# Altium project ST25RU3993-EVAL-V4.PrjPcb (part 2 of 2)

## Sheet Supply-V4.SchDoc
size A4; SheetNumber: 6; PageSetup: Record=PageOptions¦CenterHorizontal=True¦CenterVertical=True¦PrintScale=0.97¦XCorrection=1.00¦YCorrection=1.00¦PrintKind=0¦BorderSize=5000000¦LeftOffset=0¦BottomOffset=0¦Orientation=2¦PaperLength=1000¦PaperWidth=1000¦Scale=100¦PaperSource=7¦PrintQuality=-4¦MediaType=1¦DitherType=10¦PaperKind=A4¦PrintScaleMode=1
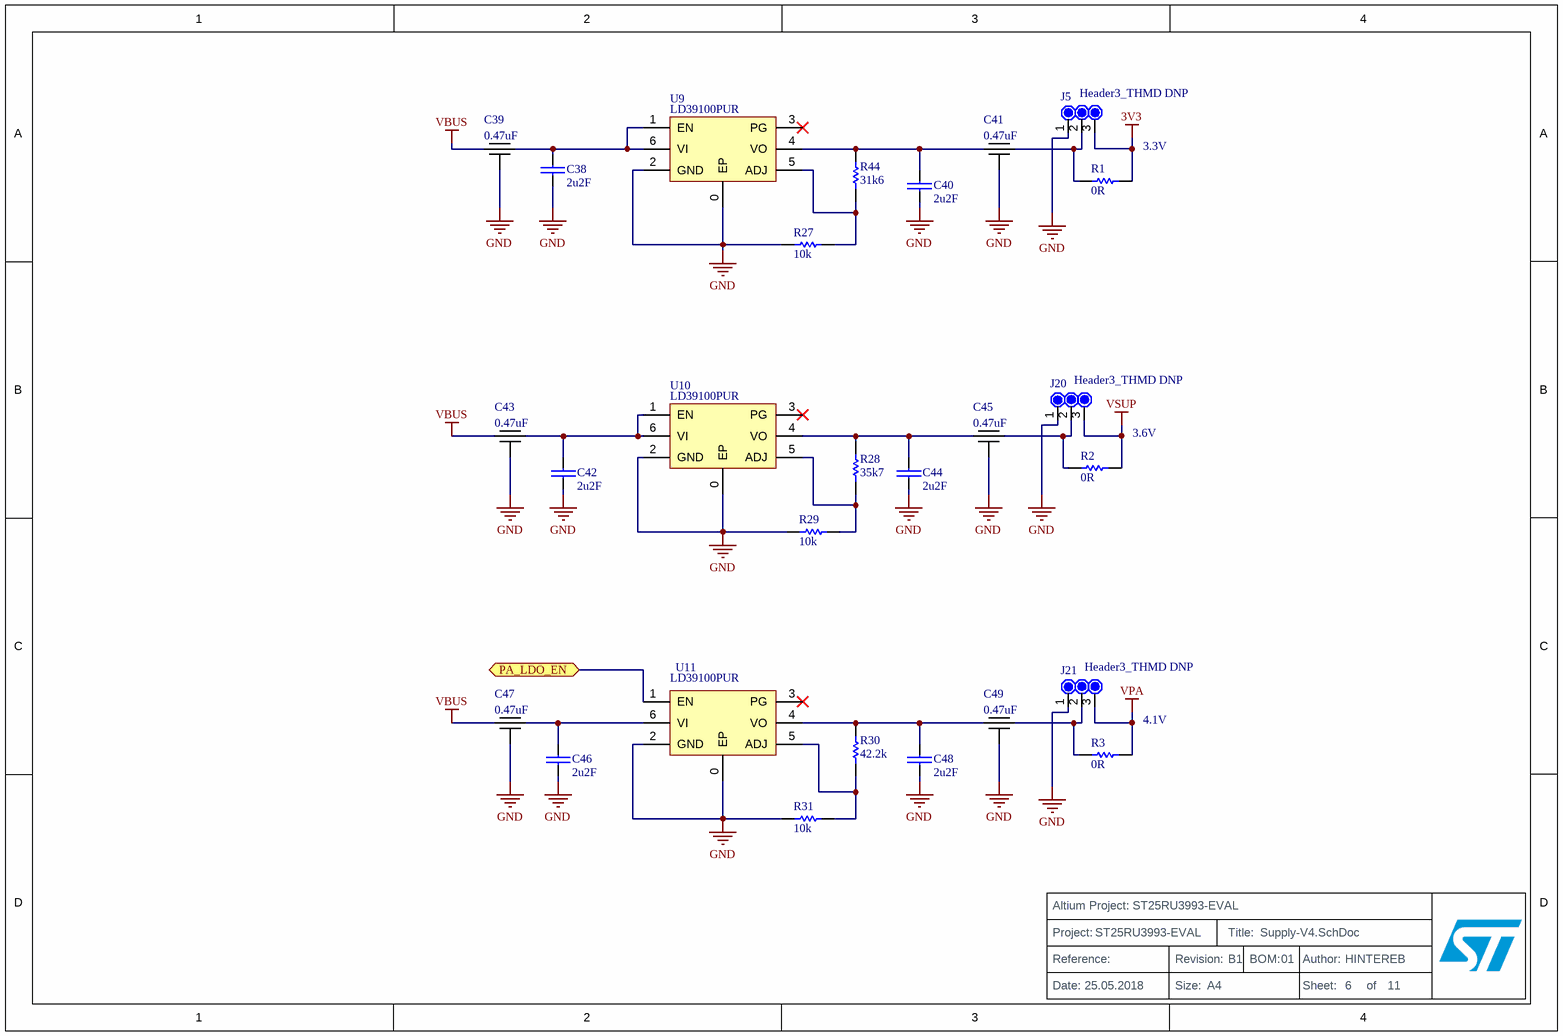
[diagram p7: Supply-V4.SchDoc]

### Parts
C38  2u2F  [C0402-RF]
C39  0.47uF  [NFM18PS]
C40  2u2F  [C0402-RF]
C41  0.47uF  [NFM18PS]
C42  2u2F  [C0402-RF]
C43  0.47uF  [NFM18PS]
C44  2u2F  [C0402-RF]
C45  0.47uF  [NFM18PS]
C46  2u2F  [C0402-RF]
C47  0.47uF  [NFM18PS]
C48  2u2F  [C0402-RF]
C49  0.47uF  [NFM18PS]
J5  Header3_THMD DNP  [PLUG_THMD_STRIP3]  (no BOM)
J20  Header3_THMD DNP  [PLUG_THMD_STRIP3]  (no BOM)
J21  Header3_THMD DNP  [PLUG_THMD_STRIP3]  (no BOM)
R1  0R  [R0603-ss]
R2  0R  [R0603-ss]
R3  0R  [R0603-ss]
R27  10k  [R0402-RF]
R28  35k7  [R0402-RF]
R29  10k  [R0402-RF]
R30  42.2k  [R0402-RF]
R31  10k  [R0402-RF]
R44  31k6  [R0402-RF]
TitleBlock4  Title_Block  (value not drawn)  (no BOM)
U9  LD39100PUR  [LD39100PUR]
U10  LD39100PUR  [LD39100PUR]
U11  LD39100PUR  [LD39100PUR]

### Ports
PA_LDO_EN (bidir)

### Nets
3V3: J5.3 R1.1
GND: C38.2 C39.2 C40.2 C41.2 C42.2 C43.2 C44.2 C45.2 C46.2 C47.2 C48.2 C49.2 J5.1 J20.1 J21.1 R27.1 R29.1 R31.1 U9.0(EP) U9.2(GND) U10.0(EP) U10.2(GND) U11.0(EP) U11.2(GND)
VBUS: C39.1 C43.1 C47.1
VPA: J21.3 R3.1
VSUP: J20.3 R2.1
PA_LDO_EN: U11.1(EN) ; port PA_LDO_EN
NetC38_1: C38.1 C39.3 U9.1(EN) U9.6(VI)
NetC40_1: C40.1 C41.1 R44.2 U9.4(VO)
NetC41_3: C41.3 J5.2 R1.2
NetC42_1: C42.1 C43.3 U10.1(EN) U10.6(VI)
NetC44_1: C44.1 C45.1 R28.2 U10.4(VO)
NetC45_3: C45.3 J20.2 R2.2
NetC46_1: C46.1 C47.3 U11.6(VI)
NetC48_1: C48.1 C49.1 R30.2 U11.4(VO)
NetC49_3: C49.3 J21.2 R3.2
NetR27_2: R27.2 R44.1 U9.5(ADJ)
NetR28_1: R28.1 R29.2 U10.5(ADJ)
NetR30_1: R30.1 R31.2 U11.5(ADJ)

Not connected (* = marked no-connect by the designer): U9 3(PG)*; U10 3(PG)*; U11 3(PG)*

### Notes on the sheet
- 3.3V
- 3.6V
- 4.1V

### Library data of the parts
C38 C40 C42 C44 C46 C48 = GRM155R60J225ME95D: CAP CER 2.2UF 6.3V  X5R  0402; Manufacturer: Murata Electronics North America; Tolerance: ±20%; Notification: Current market demand for these product types have resulted in fluctuating and extending lead times. Lead times may differ.; Exact Component Match: no
C39 C41 C43 C45 C47 C49 = NFM18PS474R0J3D: CAP FEEDTHRU 0.47UF 6.3V 0603; Manufacturer: Murata Electronics North America; Capacitance: 0.47µF; Tolerance: ±20%; Current: 2A; DC Resistance (DCR) (Max): 30 mOhm; Type: Polymer; ESR (Equivalent Series Resistance): 70 mOhm; Lifetime @ Temp.: 1000 Hrs @ 105°C; Ripple Current - High Frequency: 1A @ 100kHz; Surface Mount Land Size: 0.287" L x 0.169" W (7.30mm x 4.30mm); Exact Component Match: no
J5 J20 J21 = Pin_Header_x3: Manufacturer: Wurth Electronics Inc.; Manufacturer Part Number: 61300311121; Connector Type: Header; Pitch - Mating: 0.100" (2.54mm); Number of Positions: 3; Number of Positions Loaded: All; Style: Board to Board or Cable; Shrouding: Unshrouded; Contact Length - Mating: 0.236" (6.00mm); Contact Length - Post: 0.118" (3.00mm); Overall Contact Length: 0.454" (11.54mm); Material Flammability Rating: UL94 V-0; Current Rating: 3A; Voltage Rating: 250V; Exact Component Match: no
R1-R3 = RC0603JR-070RL: RES SMD 0.0OHM JUMPER 1/10W 0603; Manufacturer: Yageo; Exact Component Match: no
R27 R29 R31 = RC0402FR-0710KL: RES SMD 10K OHM 1% 1/16W 0402; Manufacturer 1: Yageo; Power (Watts): 0.063W, 1/16W; Temperature Coefficient: ±100ppm/°C; Exact Component Match: no
R28 = RC0402FR-0735K7L: RES SMD 35.7K OHM 1% 1/16W 0402; Manufacturer: Yageo; Power (Watts): 0.063W, 1/16W; Temperature Coefficient: ±100ppm/°C; Exact Component Match: no
R30 = ERJ-2RKF4222X: RES SMD 42.2K OHM 1% 1/10W 0402; Manufacturer: Panasonic Electronic Components; Power (Watts): 0.1W, 1/10W; Temperature Coefficient: ±100ppm/°C; Exact Component Match: no
R44 = RC0402FR-0731K6L: RES SMD 31.6K OHM 1% 1/16W 0402; Manufacturer: Yageo; Power (Watts): 0.063W, 1/16W; Temperature Coefficient: ±100ppm/°C; Exact Component Match: no
TitleBlock4 = Title_Block: Exact Component Match: no
U9-U11 = LD39100PUR: IC REG LDO ADJ 1A 6DFN; Manufacturer: STMicroelectronics; Regulator Topology: Positive Adjustable; Voltage - Output: 0.8 V ~ 4.5 V; Voltage - Dropout (Typical): 0.2V @ 1A; Number of Regulators: 1; Voltage - Input: 1.5 V ~ 5.5 V; Exact Component Match: no

## Sheet Title_Page-V4.SchDoc
size A4
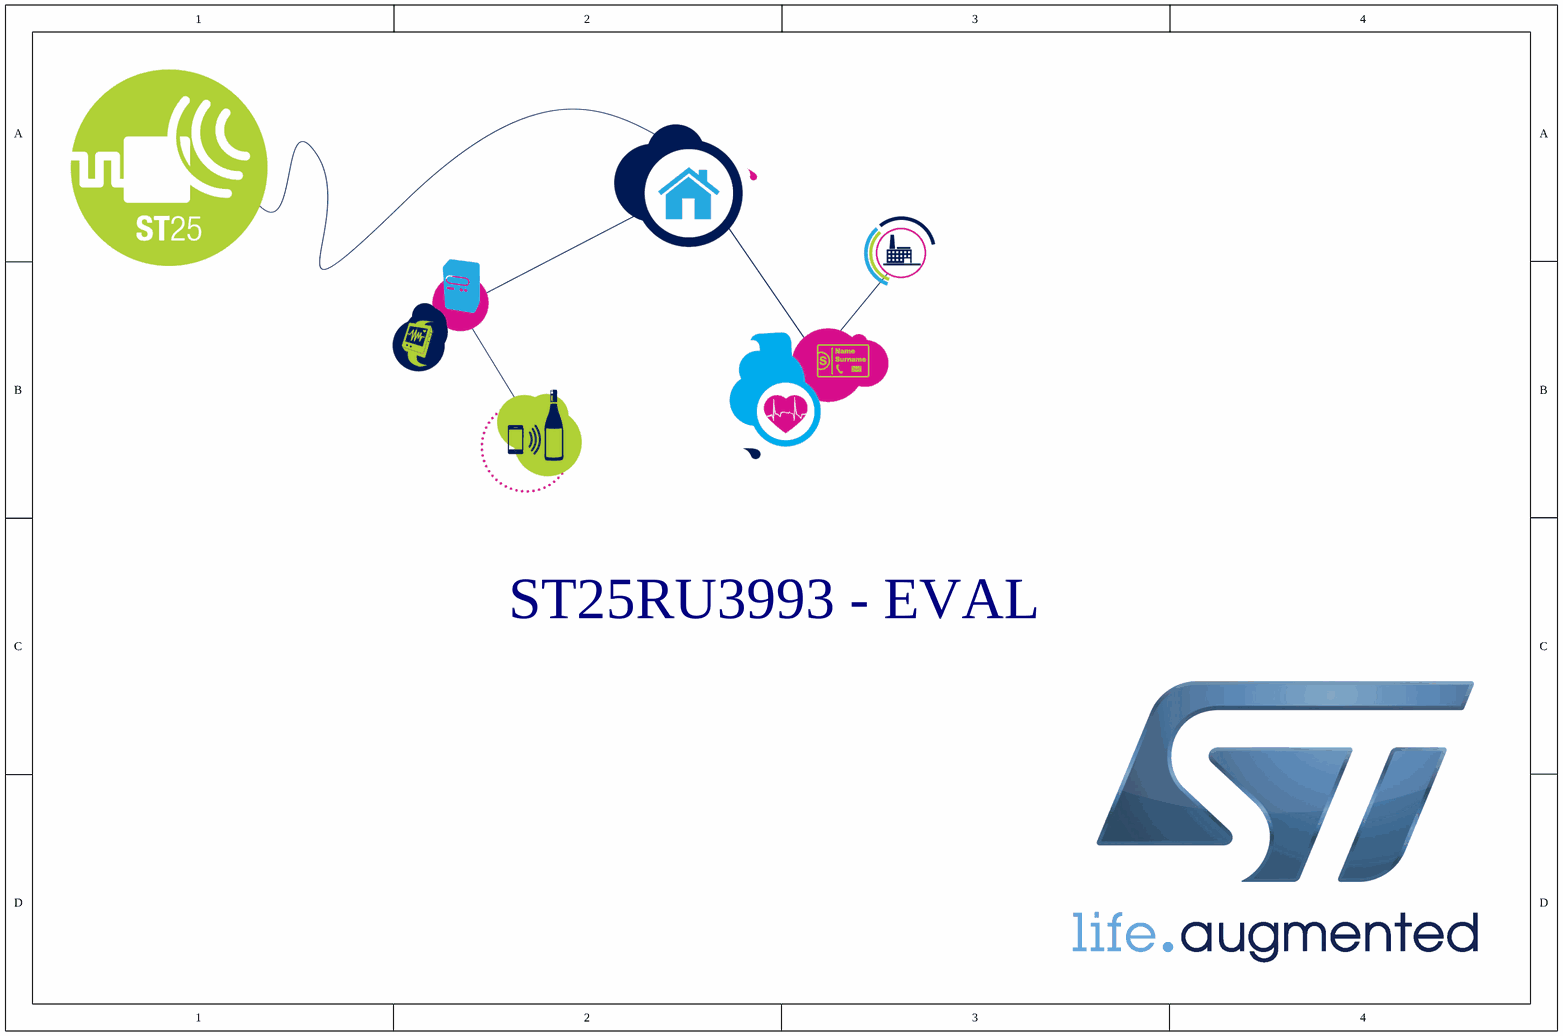
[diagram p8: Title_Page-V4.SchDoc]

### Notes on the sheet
- ST25RU3993 - EVAL

## Sheet USB_Interface-V4.SchDoc
size A4; SheetNumber: 8
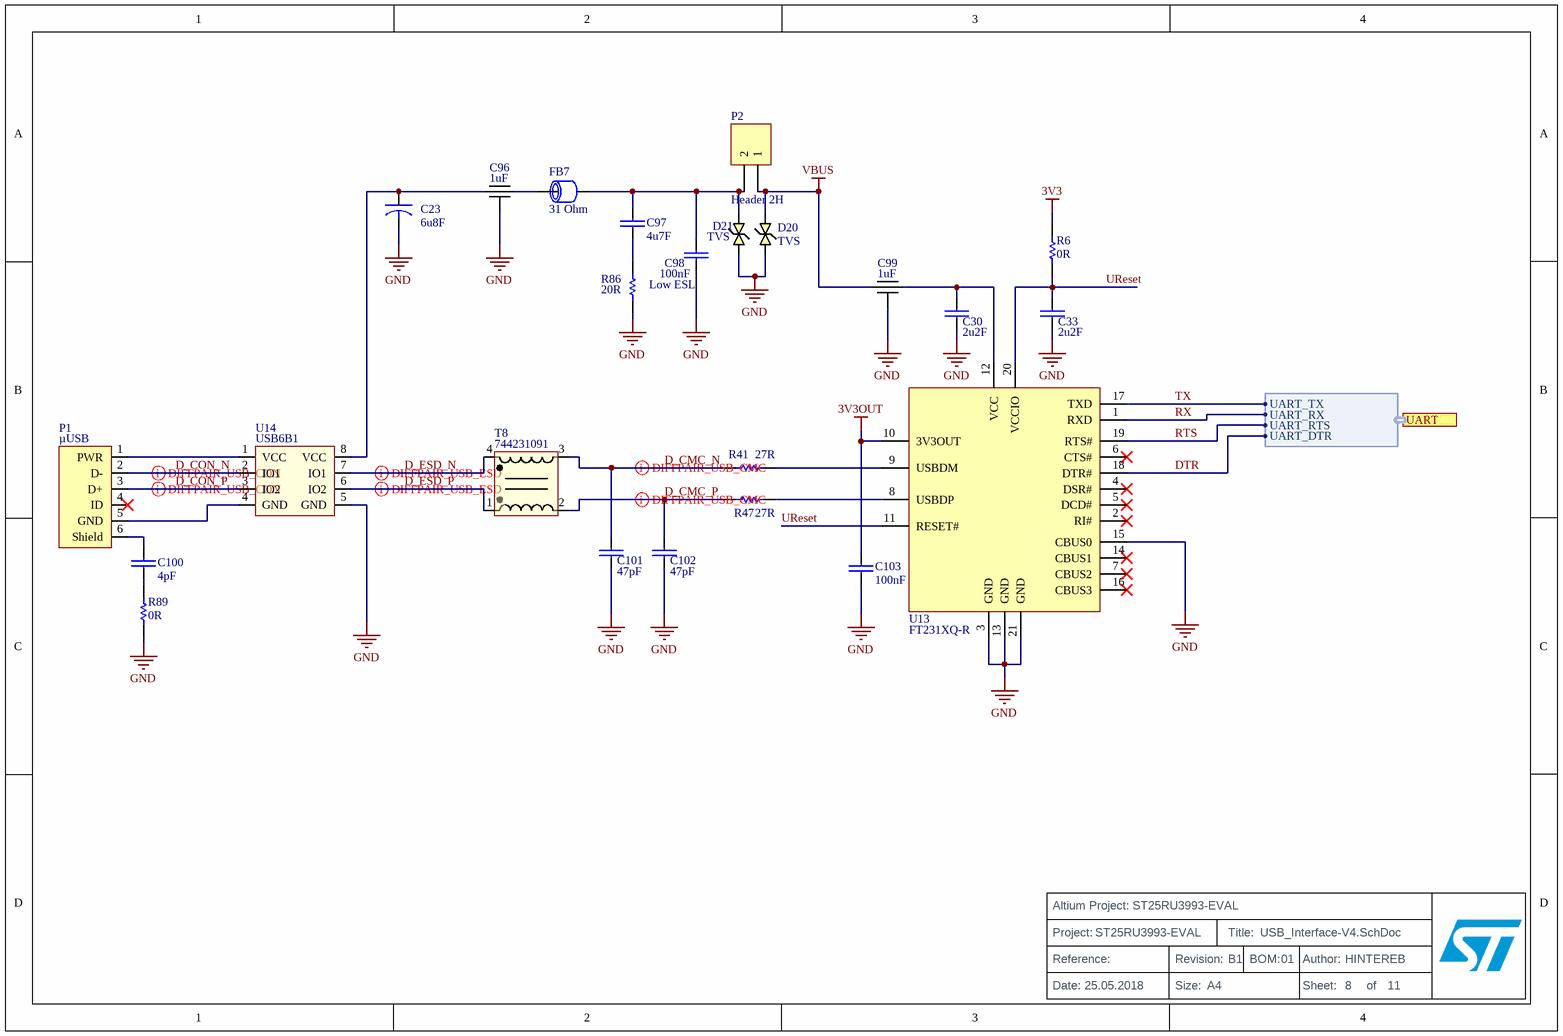
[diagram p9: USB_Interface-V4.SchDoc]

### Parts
C23  6u8F  [2917(7343)]
C30  2u2F  [C0201-RF]
C33  2u2F  [C0201-RF]
C96  1uF  [NFM21PC]
C97  4u7F  [C0603-ss]
C98  100nF  Features: Low ESL  [C0402-LLL]
C99  1uF  [NFM21PC]
C100  4pF  [C0402-ss]
C101  47pF  [C0402-RF]
C102  47pF  [C0402-RF]
C103  100nF  [C0201-ss]
D20  TVS  [DFN35P60X33-2N]
D21  TVS  [DFN35P60X33-2N]
FB7  31 Ohm  [NFZ32BW310HN11]
P1  µUSB  [µUSB Molex]
P2  Header 2H  [PLUG_THMD_STRIP2 - 90°]
R6  0R  [R0402-RF]
R41  27R  [R0402-RF]
R47  27R  [R0402-RF]
R86  20R  [R0402-RF]
R89  0R  [R0402-RF]
T8  744231091  [744231091]
TitleBlock10  Title_Block  (value not drawn)  (no BOM)
U13  FT231XQ-R  [FT231XQ]
U14  USB6B1  [SO-8]

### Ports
UART (harness Harness_UART)

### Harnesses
Harness_UART: UART_RTS, UART_DTR, UART_TX, UART_RX

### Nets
3V3: R6.1
3V3OUT: C103.1 U13.10(3V3OUT)
GND: C23.2 C30.2 C33.2 C96.2 C98.2 C99.2 C101.2 C102.2 C103.2 D20.2 D21.2 R86.1 R89.2 U13.3(GND) U13.13(GND) U13.15(CBUS0) U13.21(GND) U14.5(GND)
VBUS: C99.1 D20.1 P2.1
D_CMC_N: C101.1 R41.1 T8.3
D_CMC_P: C102.1 R47.1 T8.2
D_CON_N: P1.2(D-) U14.2(IO1)
D_CON_P: P1.3(D+) U14.3(IO2)
D_ESD_N: T8.4 U14.7(IO1)
D_ESD_P: T8.1 U14.6(IO2)
DTR: U13.18(DTR#) ; port UART.UART_DTR
RTS: U13.19(RTS#) ; port UART.UART_RTS
RX: U13.1(RXD) ; port UART.UART_RX
TX: U13.17(TXD) ; port UART.UART_TX
UReset: C33.1 R6.2 U13.11(RESET#) U13.20(VCCIO)
NetC23_1: C23.1 C96.1 U14.8(VCC)
NetC30_1: C30.1 C99.3 U13.12(VCC)
NetC96_3: C96.3 FB7.1
NetC97_1: C97.1 C98.1 D21.1 FB7.2 P2.2
NetC97_2: C97.2 R86.2
NetC100_1: C100.1 P1.6(Shield)
NetC100_2: C100.2 R89.1
NetP1_1: P1.1(PWR) U14.1(VCC)
NetP1_5: P1.5(GND) U14.4(GND)
NetR41_2: R41.2 U13.9(USBDM)
NetR47_2: R47.2 U13.8(USBDP)

Not connected (* = marked no-connect by the designer): P1 4(ID)*; U13 2(RI#)* 4(DSR#)* 5(DCD#)* 6(CTS#)* 7(CBUS2)* 14(CBUS1)* 16(CBUS3)*

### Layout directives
differential pair: D_CMC_N, D_CMC_P, D_CON_N, D_CON_P, D_ESD_N, D_ESD_P

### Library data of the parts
C23 = ECASD41C685M070K00: CAP ALUM POLY 6.8UF 20% 16V SMD; Manufacturer: Murata Electronics North America; Type: Polymer; ESR (Equivalent Series Resistance): 70 mOhm; Lifetime @ Temp.: 1000 Hrs @ 105°C; Ripple Current - High Frequency: 1A @ 100kHz; Surface Mount Land Size: 0.287" L x 0.169" W (7.30mm x 4.30mm); Exact Component Match: no
C30 C33 = GRM033R60J225ME15D: CAP CER 2.2UF 6.3V X5R 0201; Manufacturer 1: Murata Electronics North America; Capacitance: 2.2µF; Tolerance: ±20%; Exact Component Match: no
C96 C99 = NFM21PC105B1A3D: CAP FEEDTHRU 1UF 20% 10V 0805; Manufacturer: Murata Electronics North America; Capacitance: 1µF; Current: 4A; DC Resistance (DCR) (Max): 20 mOhm; Coupler Type: Standard; Frequency: 1.7GHz ~ 2.2GHz; Coupling Factor: 19.9dB; Power - Max: 2W; Return Loss: 22.5dB; Exact Component Match: no
C97 = GRM188R61A475KE15D: CAP CER 4.7UF 10V X5R 0603; Manufacturer: Murata Electronics North America; Tolerance: ±10%; Notification: Current market demand for these product types have resulted in fluctuating and extending lead times. Lead times may differ.; Exact Component Match: no
C98 = LLL153C80J104ME01E: CAP CER 0.1UF 6.3V X6S 0204; Manufacturer: Murata Electronics North America; Tolerance: ±20%; Type: Steering (Rail to Rail); Voltage - Reverse Standoff (Typ): 5.25V; Voltage - Breakdown (Min): 6V; Power - Peak Pulse: 500W; Power Line Protection: Yes; Exact Component Match: no
C100 = GRM1555C1H4R0CA01D: CAP CER 4PF 50V C0G/NP0 0402; Manufacturer: Murata Electronics North America; Tolerance: ±0.25pF; Temperature Coefficient: C0G, NP0; Notification: Current market demand for these product types have resulted in fluctuating and extending lead times. Lead times may differ.; Exact Component Match: no
C101 C102 = GRM1555C1H470FA01D: CAP CER 47PF 50V NP0 0402; Manufacturer: Murata Electronics North America; Tolerance: ±1%; Temperature Coefficient: C0G, NP0; Exact Component Match: no
C103 = GRM033C80J104KE15D: CAP CER 0.1UF 6.3V X6S 0201; Manufacturer 1: Murata Electronics North America; Capacitance: 0.10µF; Tolerance: ±10%; Exact Component Match: no
D20 D21 = ESDAXLC6-1BU2: TVS DIODE 3VWM 17VC ST0201; Manufacturer: STMicroelectronics; Type: Zener; Voltage - Reverse Standoff (Typ): 3V; Voltage - Breakdown (Min): 6V; Voltage - Clamping (Max) @ Ipp: 17V; Current - Peak Pulse (10/1000µs): 1A (8/20µs); Power - Peak Pulse: 40W; Power Line Protection: No; Capacitance @ Frequency: 0.4pF @ 200MHz ~ 3GHz; Tolerance: ±1%; Power (Watts): 0.1W, 1/10W; Temperature Coefficient: ±100ppm/°C
FB7 = NFZ32BW310HN11L: FERRITE BEAD 31 OHM 2SMD 1LN; Manufacturer: Murata Electronics North America; Current Rating (Max): 1.2A; DC Resistance (DCR) (Max): 186 mOhm; Exact Component Match: no
P1 = µUSB: Micro USB Connector; Manufacturer: Molex, LLC; Manufacturer Part Number: 1050170001; Connector Type: USB - micro B; Number of Contacts: 5; Gender: Receptacle; Specifications: USB 2.0; Number of Ports: 1; Current Rating: 1A, 1.8A; Voltage - Rated: 30VAC; Mating Cycles: 10000; Shielding: Shielded; Material Flammability Rating: UL94 V-0; Exact Component Match: no
P2 = Header 2H: Header, 2-Pin, Right Angle; Exact Component Match: no
R6 R89 = RC0402JR-070RL: RES SMD 0.0OHM JUMPER 1/16W 0402; Manufacturer: Yageo; Resistance (Ohms): 0.0; Power (Watts): 0.063W, 1/16W; Exact Component Match: no
R41 R47 = RC0402FR-0727RL: RES SMD 27 OHM 1% 1/16W 0402; Manufacturer: Yageo; Resistance (Ohms): 27; Power (Watts): 0.063W, 1/16W; Temperature Coefficient: ±100ppm/°C; Exact Component Match: no
R86 = RC0402JR-0720RL: RES SMD 20 OHM 5% 1/16W 0402; Manufacturer 1: Yageo; Resistance (Ohms): 20; Power (Watts): 0.063W, 1/16W; Temperature Coefficient: ±100ppm/°C; Frequency: 915MHz Center; Bandwidth: 26MHz; Filter Type: Low Pass; Insertion Loss: 0.5dB; Exact Component Match: no
T8 = 744231091: CHOKE COM MODE 90 OHM .37A SMD; Manufacturer: Wurth Electronics Inc.; Filter Type: Signal Line; Number of Lines: 2; Current Rating (Max): 370mA; DC Resistance (DCR) (Max): 300 mOhm; Voltage Rating - DC: 50V; Exact Component Match: no
TitleBlock10 = Title_Block: Exact Component Match: no
U13 = FT231XQ-R: IC USB SERIAL FULL UART 20QFN; Manufacturer: FTDI, Future Technology Devices International Ltd; Function: Bridge, USB to UART; Standards: USB 2.0; Voltage - Supply: 3.3 V ~ 5 V; Current - Supply: 8mA; Exact Component Match: no
U14 = USB6B1RL: TVS DIODE 5.25VWM 8SOIC; Manufacturer: STMicroelectronics; Voltage - Reverse Standoff (Typ): 5.25V; Voltage - Breakdown (Min): 6V; Power - Peak Pulse: 500W; Power Line Protection: Yes; Exact Component Match: no

## Sheet Bluetooth-V4.SchDoc
size A4; SheetNumber: 10
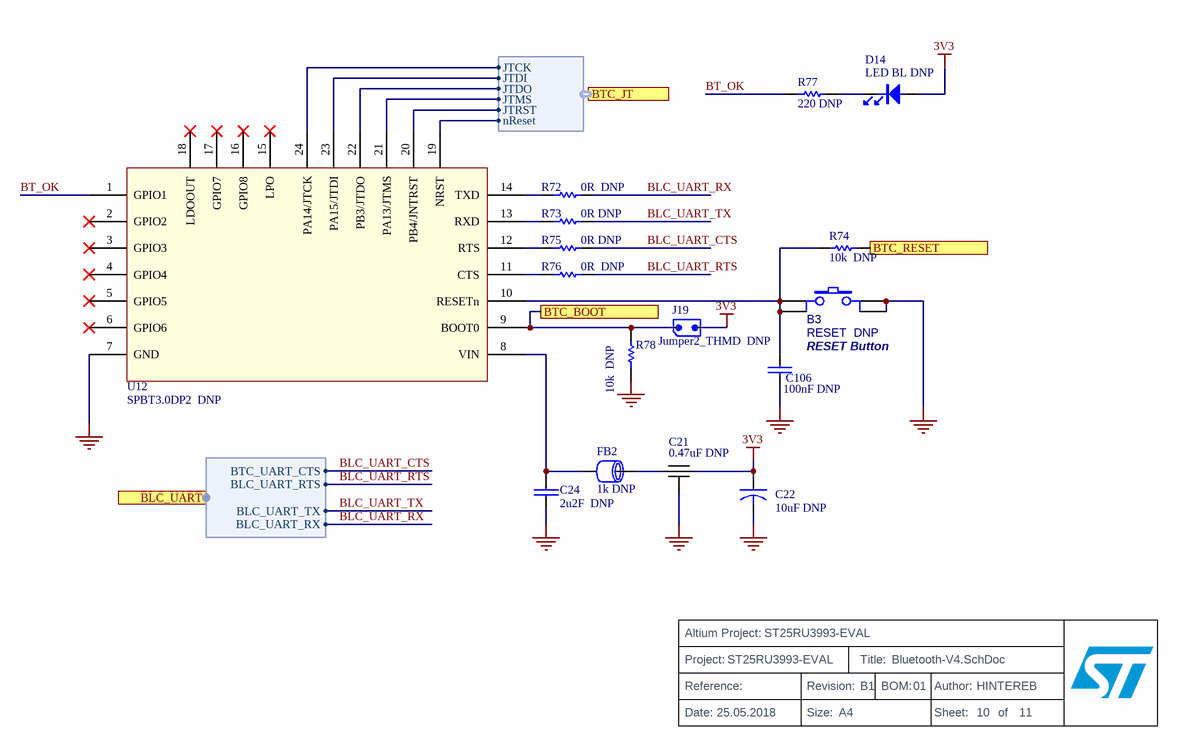
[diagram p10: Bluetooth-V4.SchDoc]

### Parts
B3  RESET  DNP  [SW_SPST_KMR211G]
C21  0.47uF DNP  [NFM18PS]
C22  10uF DNP  [2917(7343)]
C24  2u2F  DNP  [C0201-RF]
C106  100nF DNP  [C0402-RF]
D14  LED BL DNP  [LNJ947W8CRA]
FB2  1k DNP  [L0402-RF]
J19  Jumper2_THMD  DNP  [PLUG_THMD_STRIP2 - DNP]
R72  0R  DNP  [R0402-RF]
R73  0R DNP  [R0402-RF]
R74  10k  DNP  [R0402-RF]
R75  0R DNP  [R0402-RF]
R76  0R  DNP  [R0402-RF]
R77  220 DNP
R78  10k  DNP  [R0402-RF]
TitleBlock9  Title_Block  (value not drawn)  (no BOM)
U12  SPBT3.0DP2  DNP  [SPBT3.0DP2]

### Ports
BLC_UART (harness Harness_UART_BT), BTC_BOOT, BTC_JT (harness Harness_BTC_JT), BTC_RESET

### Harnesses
Harness_UART_BT: BLC_UART_RTS, BTC_UART_CTS, BLC_UART_TX, BLC_UART_RX
Harness_BTC_JT: JTMS, JTRST, nReset, JTDO, JTDI, JTCK

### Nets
3V3: C21.1 C22.1 D14.1 J19.2
GND: B3.2 B3.3 C21.2 C22.2 C24.2 C106.2 R78.1 U12.7(GND)
BLC_UART_CTS: R75.2 ; port BLC_UART.BTC_UART_CTS
BLC_UART_RTS: R76.2 ; port BLC_UART.BLC_UART_RTS
BLC_UART_RX: R72.2 ; port BLC_UART.BLC_UART_RX
BLC_UART_TX: R73.2 ; port BLC_UART.BLC_UART_TX
BT_OK: R77.1 U12.1(GPIO1)
JTCK: U12.24(PA14/JTCK) ; port BTC_JT.JTCK
JTDI: U12.23(PA15/JTDI) ; port BTC_JT.JTDI
JTDO: U12.22(PB3/JTDO) ; port BTC_JT.JTDO
JTMS: U12.21(PA13/JTMS) ; port BTC_JT.JTMS
JTRST: U12.20(PB4/JNTRST) ; port BTC_JT.JTRST
nReset: U12.19(NRST) ; port BTC_JT.nReset
NetB3_1: B3.1 B3.4 C106.1 R74.2 U12.10(RESETn)
NetC21_3: C21.3 FB2.1
NetC24_1: C24.1 FB2.2 U12.8(VIN)
NetD14_2: D14.2 R77.2
NetJ19_1: J19.1 R78.2 U12.9(BOOT0) ; port BTC_BOOT
NetR72_1: R72.1 U12.14(TXD)
NetR73_1: R73.1 U12.13(RXD)
NetR74_1: R74.1 ; port BTC_RESET
NetR75_1: R75.1 U12.12(RTS)
NetR76_1: R76.1 U12.11(CTS)

Not connected (* = marked no-connect by the designer): U12 2(GPIO2)* 3(GPIO3)* 4(GPIO4)* 5(GPIO5)* 6(GPIO6)* 15(LPO)* 16(GPIO8)* 17(GPIO7)* 18(LDOOUT)*

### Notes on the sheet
- RESET Button

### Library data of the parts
B3 = SW-PUSH-CMS_BLACK_1: Non-Open Push-Button 0.1A 24V; Manufacturer 1: C&K Components; Manufacturer Part Number 1: KMR211NG LFS; Circuit: SPST-NO; Switch Function: Off-Mom; Contact Rating @ Voltage: 0.05A @ 32VDC; Actuator Type: Standard; Actuator Height off PCB, from Pins: 1.90mm; Actuator Orientation: Top Actuated; Outline: 4.60mm x 2.80mm; Illumination: Non-Illuminated; Operating Force: 120gf; Switch Travel: 0.20mm; Mechanical Life: 200,000 Cycles; Exact Component Match: no
C21 = NFM18PS474R0J3D: as C39 on sheet Supply-V4
C22 = ECASD41C106M060K00: CAP POLYMER 10UF 20% 16V SMD; Manufacturer: Murata; Product Training Modules: Polymer Aluminum Electrolytic Capacitors Using Murata's Polymer Aluminum Capacitors to Replace Tantalum; Catalog Drawings: ECAS Series End_D4 ECAS Series Side; Featured Product: ECAS Series Polymer Aluminum Electrolytic Capacitors; EDA / CAD Models: Download from Accelerated Designs; Capacitance: 10µF; ESR (Equivalent Series Resistance): 60 mOhm @ 100kHz; Lifetime @ Temp.: 1000 Hrs @ 105°C; Polarization: Polar; Ripple Current: 1A; Surface Mount Land Size: 0.287" L x 0.169" W (7.30mm x 4.30mm); Online Catalog: ECAS Series; Other Names: 490-5482-2; Exact Component Match: no
C24 = GRM033R60J225ME15D: as C30 on sheet USB_Interface-V4
C106 = GRM155R71C104KA88D: CAP CER 0.1UF 16V X7R 0402; Manufacturer: Murata Electronics North America; Capacitance: 0.10µF; Tolerance: ±10%; Exact Component Match: no
D14 = LNJ947W8CRA: LED BLUE 0402 SMD; Manufacturer 1: Panasonic Electronic Components; Millicandela Rating: 18mcd; Lens Style/Size: Rectangle with Flat Top, 0.70mm x 0.50mm; Voltage - Forward (Vf) (Typ): 2.9V; Current - Test: 5mA; Wavelength - Dominant: 472nm; Wavelength - Peak: 465nm; Exact Component Match: no
FB2 = BLM15HG102SN1D: FERRITE BEAD 1 KOHM 0402 1LN; Manufacturer: Murata Electronics North America; Filter Type: Signal Line; Number of Lines: 1; Impedance @ Frequency: 1 kOhm @ 100MHz; Current Rating (Max): 250mA; DC Resistance (DCR) (Max): 1.1 Ohm; Exact Component Match: no
J19 = Jumper2_THMD: Manufacturer: Amphenol FCI; Manufacturer Part Number: 77311-118-02LF; Connector Type: Header; Pitch - Mating: 0.100" (2.54mm); Style: Board to Board; Shrouding: Unshrouded; Number of Positions: 2; Number of Positions Loaded: All; Contact Length - Mating: 0.230" (5.84mm); Contact Length - Post: 0.120" (3.05mm); Overall Contact Length: 0.450" (11.43mm); Material Flammability Rating: UL94 V-0; Exact Component Match: no
R72 R73 R75 R76 = RC0402JR-070RL: as R6 on sheet USB_Interface-V4
R74 R78 = RC0402FR-0710KL: as R27 on sheet Supply-V4
R77 = RC0402JR-07220RL: RES SMD 220 OHM 5% 1/16W 0402; Manufacturer: Yageo; Power (Watts): 0.063W, 1/16W; Temperature Coefficient: ±100ppm/°C; Exact Component Match: no
TitleBlock9 = Title_Block: Exact Component Match: no
U12 = SPBT3: SPBT3.0DP2 BLUETOOTH 3.0; Manufacturer: STMICROELECTRONICS; Kit Application Type: Wireless Connectivity; Exact Component Match: no

## Sheet Mechanical-V4.SchDoc
size A4; SheetNumber: 11
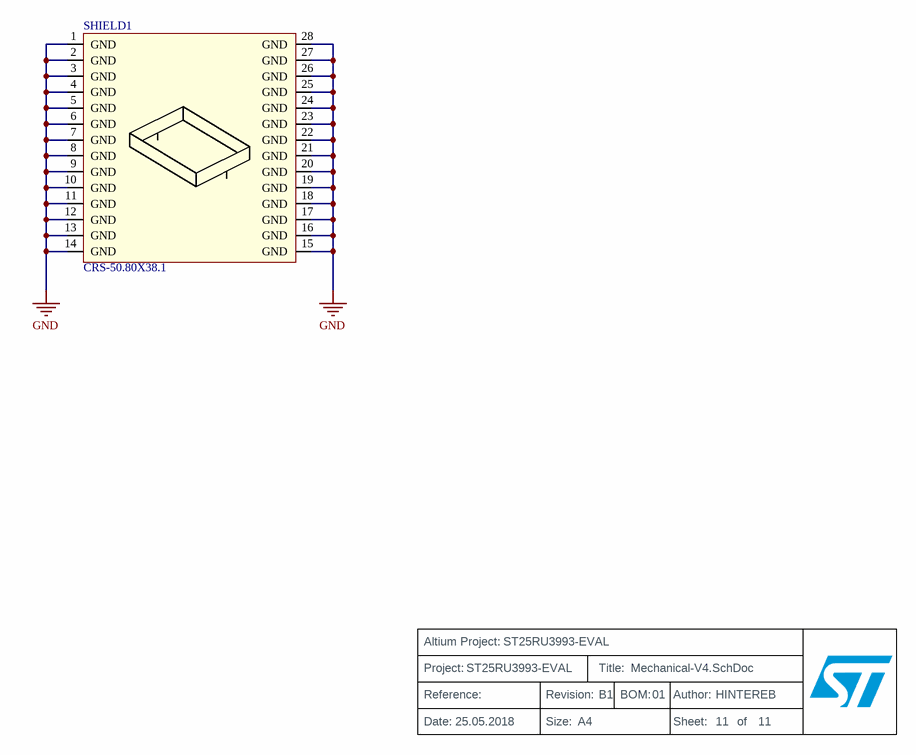
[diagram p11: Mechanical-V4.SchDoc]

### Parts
SHIELD1  CRS-50.80X38.1  [RF Shield - 50.8 x 38.1 mm]
TitleBlock8  Title_Block  (value not drawn)  (no BOM)

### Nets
GND: SHIELD1.1(GND) SHIELD1.2(GND) SHIELD1.3(GND) SHIELD1.4(GND) SHIELD1.5(GND) SHIELD1.6(GND) SHIELD1.7(GND) SHIELD1.8(GND) SHIELD1.9(GND) SHIELD1.10(GND) SHIELD1.11(GND) SHIELD1.12(GND) SHIELD1.13(GND) SHIELD1.14(GND) SHIELD1.15(GND) SHIELD1.16(GND) SHIELD1.17(GND) SHIELD1.18(GND) SHIELD1.19(GND) SHIELD1.20(GND) SHIELD1.21(GND) SHIELD1.22(GND) SHIELD1.23(GND) SHIELD1.24(GND) SHIELD1.25(GND) SHIELD1.26(GND) SHIELD1.27(GND) SHIELD1.28(GND)

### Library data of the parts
SHIELD1 = 2118732-2: RF Shield 51.1 x 38.4 x 6.5; Manufacturer: TE Connectivity AMP Connectors
TitleBlock8 = Title_Block: Exact Component Match: no

## Sheet Antenna_Switch-V4.SchDoc
size A4; SheetNumber: 9; PageSetup: Record=PageOptions¦CenterHorizontal=True¦CenterVertical=True¦PrintScale=0.97¦XCorrection=1.00¦YCorrection=1.00¦PrintKind=0¦BorderSize=5000000¦LeftOffset=0¦BottomOffset=0¦Orientation=2¦PaperLength=1000¦PaperWidth=1000¦Scale=100¦PaperSource=7¦PrintQuality=-4¦MediaType=1¦DitherType=10¦PaperKind=A4¦PrintScaleMode=1
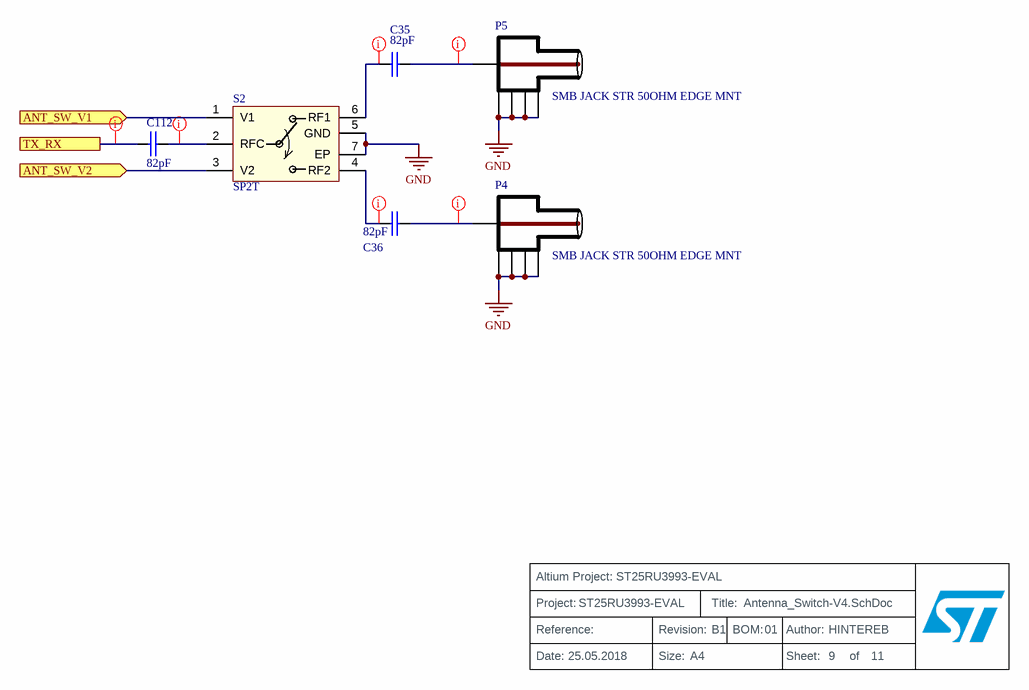
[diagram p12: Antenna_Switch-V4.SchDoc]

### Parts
C35  82pF  [C0402-RF]
C36  82pF  [C0402-RF]
C112  82pF  [C0402-RF]
P4  SMB JACK STR 50OHM EDGE MNT  [903-723J-51S]
P5  SMB JACK STR 50OHM EDGE MNT  [903-723J-51S]
S2  SP2T  [SKY13431-374LF]
TitleBlock11  Title_Block  (value not drawn)  (no BOM)

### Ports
ANT_SW_V1 (in), ANT_SW_V2 (in), TX_RX

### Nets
GND: P4.2 P4.3 P4.4 P4.5 P5.2 P5.3 P5.4 P5.5 S2.5(GND) S2.7(EP)
NetC35_1: C35.1 S2.6(RF1)
NetC35_2: C35.2 P5.1
NetC36_1: C36.1 S2.4(RF2)
NetC36_2: C36.2 P4.1
NetC112_1: C112.1 S2.2(RFC)
NetC112_2: C112.2 ; port TX_RX
NetS2_1: S2.1(V1) ; port ANT_SW_V1
NetS2_3: S2.3(V2) ; port ANT_SW_V2

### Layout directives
net class SE_CPWG: NetC35_1, NetC35_2, NetC36_1, NetC36_2, NetC112_1, NetC112_2

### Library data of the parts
C35 C36 C112 = GRM1555C1H820GA01J: CAP CER 82PF 50V C0G/NP0 0402; Manufacturer: Murata Electronics North America; Tolerance: ±2%; Temperature Coefficient: C0G, NP0; Filter Type: Signal Line; Number of Lines: 1; Impedance @ Frequency: 1 kOhm @ 100MHz; Current Rating (Max): 250mA; DC Resistance (DCR) (Max): 1.1 Ohm; Type: Zener; Voltage - Reverse Standoff (Typ): 3V; Voltage - Breakdown (Min): 6V; Voltage - Clamping (Max) @ Ipp: 17V; Current - Peak Pulse (10/1000µs): 1A (8/20µs); Power - Peak Pulse: 40W; Power Line Protection: No; Capacitance @ Frequency: 0.4pF @ 200MHz ~ 3GHz
P4 P5 = 903-723J-51S: CONN SMB JACK STR 50OHM EDGE MNT; Manufacturer: Amphenol RF Division; Connector Type: Jack, Male Pin; Contact Termination: Solder; Shield Termination: Crimp; Body Material: Zinc Die Cast; Body Finish: Tin; Center Contact Plating: Gold; Dielectric Material: Polytetrafluoroethylene (PTFE); Center Contact Material: Brass; Mating Cycles: 100; Insertion Loss: 0.3dB
S2 = SKY13431-374LF: IC SWITCH SP2T; Manufacturer: Skyworks Solutions Inc.; Frequency - Lower: 500MHz; Isolation @ Frequency: 20dB @ 5.8GHz (typ); Insertion Loss @ Frequency: 0.8dB @ 5.8GHz; IIP3: 57dBm (typ); Circuit: SPDT; P1dB: 36dBm; Impedance: 50 Ohm; Voltage - Supply: 2.5 V ~ 5 V; RF Type: WiMax, WLAN; Exact Component Match: no
TitleBlock11 = Title_Block: Exact Component Match: no

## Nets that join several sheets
3V3: UHF_RFID-V4 (C50.1 C69.1 FB4.1 U5.38), Power_Amplifier-V4 (C15.1 C70.1 U3.2 U3.8), External_Interfaces-V4 (J14.7 P3.1), Controller-V4 (27 pins), Carrier_Cancellation-V4 (9 pins), Supply-V4 (J5.3 R1.1), USB_Interface-V4 (R6.1), Bluetooth-V4 (C21.1 C22.1 D14.1 J19.2)
GND: UHF_RFID-V4 (57 pins), Power_Amplifier-V4 (33 pins), External_Interfaces-V4 (42 pins), Controller-V4 (21 pins), Carrier_Cancellation-V4 (26 pins), Supply-V4 (24 pins), USB_Interface-V4 (18 pins), Bluetooth-V4 (8 pins), Mechanical-V4 (28 pins), Antenna_Switch-V4 (10 pins)
VBUS: Supply-V4 (C39.1 C43.1 C47.1), USB_Interface-V4 (C99.1 D20.1 P2.1)
VPA: Power_Amplifier-V4 (C16.3 C20.1 C104.1), Supply-V4 (J21.3 R3.1)
VSUP: UHF_RFID-V4 (C91.3 C92.1), Supply-V4 (J20.3 R2.1)
ADC: UHF_RFID-V4 (U5.39), External_Interfaces-V4 (D38.1 J12.6)
BLC_UART_CTS: Controller-V4 (U1.44), Bluetooth-V4 (R75.2)
BLC_UART_RTS: Controller-V4 (U1.45), Bluetooth-V4 (R76.2)
BLC_UART_RX: Controller-V4 (U1.59), Bluetooth-V4 (R72.2)
BLC_UART_TX: Controller-V4 (U1.58), Bluetooth-V4 (R73.2)
CLK: UHF_RFID-V4 (U5.37), External_Interfaces-V4 (D22.1 J10.1), Controller-V4 (R8.1), Carrier_Cancellation-V4 (U6.5 U7.5 U8.5)
Detector: Power_Amplifier-V4 (U3.7), External_Interfaces-V4 (TP4.1), Controller-V4 (U1.15)
DTR: External_Interfaces-V4 (D48.1 J7.2), Controller-V4 (R37.1), USB_Interface-V4 (U13.18)
EN: UHF_RFID-V4 (U5.31), External_Interfaces-V4 (D35.1 J12.3), Controller-V4 (R13.1)
ETC_1: External_Interfaces-V4 (D25.1 J13.1), Controller-V4 (R40.2), Carrier_Cancellation-V4 (U6.6)
ETC_2: External_Interfaces-V4 (D26.1 J13.2), Controller-V4 (R39.2), Carrier_Cancellation-V4 (U7.6)
ETC_3: External_Interfaces-V4 (D27.1 J13.3), Controller-V4 (R38.2), Carrier_Cancellation-V4 (U8.6)
EXT_PA_BIAS: Power_Amplifier-V4 (R21.2 U2.1), External_Interfaces-V4 (TP3.1)
IRQ: UHF_RFID-V4 (U5.32), External_Interfaces-V4 (D36.1 J12.4), Controller-V4 (R12.1)
JTCK: External_Interfaces-V4 (D39.1 J14.3), Bluetooth-V4 (U12.24)
JTDI: External_Interfaces-V4 (D40.1 J14.5), Bluetooth-V4 (U12.23)
JTDO: External_Interfaces-V4 (D41.1 J14.2), Bluetooth-V4 (U12.22)
JTMS: External_Interfaces-V4 (D42.1 J14.4), Bluetooth-V4 (U12.21)
JTRST: External_Interfaces-V4 (D43.1 J14.1), Bluetooth-V4 (U12.20)
MISO: UHF_RFID-V4 (U5.34), External_Interfaces-V4 (D24.1 J10.3), Controller-V4 (R9.1)
MOSI: UHF_RFID-V4 (U5.35), External_Interfaces-V4 (D23.1 J10.2), Controller-V4 (R11.1), Carrier_Cancellation-V4 (U6.7 U7.7 U8.7)
NCS: UHF_RFID-V4 (U5.33), External_Interfaces-V4 (D37.1 J12.5), Controller-V4 (R7.1)
NetB1_1: External_Interfaces-V4 (R5.2), Controller-V4 (6 pins)
NetC107_1: UHF_RFID-V4 (J9.OUT), Power_Amplifier-V4 (C107.1)
NetC112_2: Carrier_Cancellation-V4 (T4.6), Antenna_Switch-V4 (C112.2)
NetJ1_IN: UHF_RFID-V4 (T5.1), Power_Amplifier-V4 (J1.IN)
NetJ19_1: Controller-V4 (U1.62), Bluetooth-V4 (J19.1 R78.2 U12.9)
NetR4_2: External_Interfaces-V4 (R4.2), Controller-V4 (U1.50)
NetR19_2: External_Interfaces-V4 (R19.2), Controller-V4 (U1.46)
NetR42_2: External_Interfaces-V4 (R42.2), Controller-V4 (U1.49)
NetR46_2: External_Interfaces-V4 (R46.2), Controller-V4 (U1.55)
NetR74_1: Controller-V4 (U1.2), Bluetooth-V4 (R74.1)
NetS1_1: Power_Amplifier-V4 (S1.1), Controller-V4 (U1.26)
NetS1_3: Power_Amplifier-V4 (S1.3), Controller-V4 (U1.25)
NetS2_1: Controller-V4 (U1.29), Antenna_Switch-V4 (S2.1)
NetS2_3: Controller-V4 (U1.30), Antenna_Switch-V4 (S2.3)
NetT2_1: Power_Amplifier-V4 (T2.1), Carrier_Cancellation-V4 (T4.1)
nReset: External_Interfaces-V4 (D44.1 J14.6), Bluetooth-V4 (U12.19)
OAD: UHF_RFID-V4 (U5.27), External_Interfaces-V4 (D34.1 J12.2)
OAD2: UHF_RFID-V4 (U5.26), External_Interfaces-V4 (D33.1 J12.1)
OSCO: UHF_RFID-V4 (C51.2 R54.1 U5.30), External_Interfaces-V4 (TP1.1)
PA_LDO_EN: External_Interfaces-V4 (D45.1 J4.1), Controller-V4 (R43.1), Supply-V4 (U11.1)
RTS: External_Interfaces-V4 (D47.1 J7.1), Controller-V4 (R36.1), USB_Interface-V4 (U13.19)
RX: External_Interfaces-V4 (D50.1 J7.4), Controller-V4 (R56.1), USB_Interface-V4 (U13.1)
RX_N: UHF_RFID-V4 (C94.1), Carrier_Cancellation-V4 (T6.3)
RX_P: UHF_RFID-V4 (C93.1), Carrier_Cancellation-V4 (T6.4)
TX: External_Interfaces-V4 (D49.1 J7.3), Controller-V4 (R57.1), USB_Interface-V4 (U13.17)
UART_LOG_TX: External_Interfaces-V4 (D52.1 J11.1), Controller-V4 (R58.2)
VCO: UHF_RFID-V4 (C55.1 R33.1), External_Interfaces-V4 (TP2.1)

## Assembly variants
No BT Module: not fitted B3 C21 C22 C24 C106 D14 FB2 J19 R35 R54 R55 R72 R73 R74 R75 R76 R77 R78 U12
